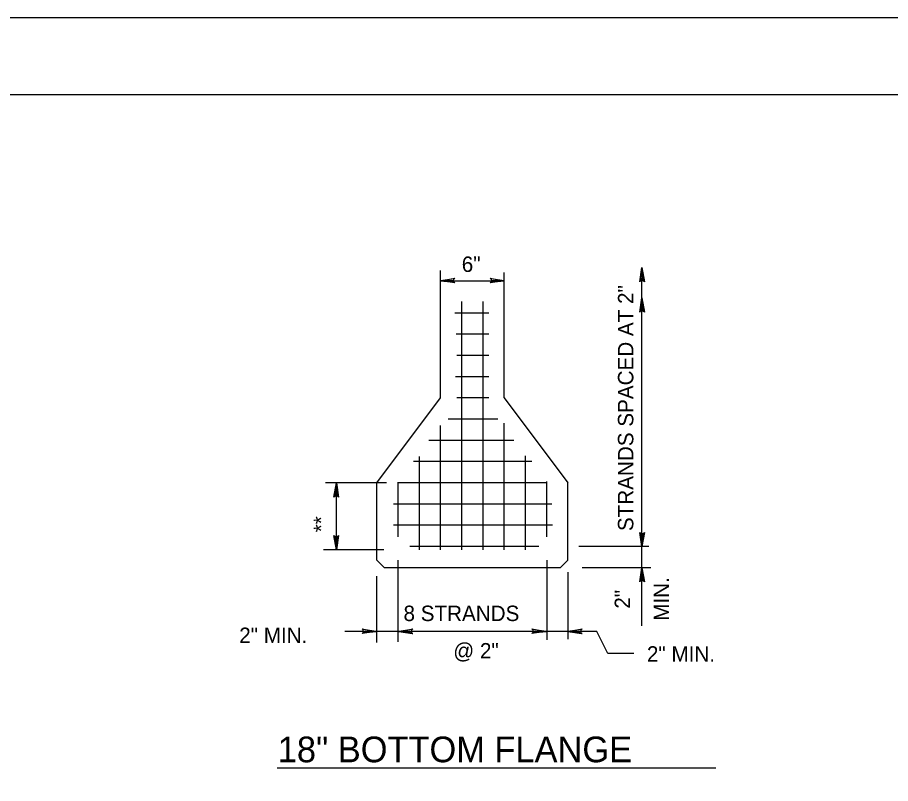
# Model space of a CAD drawing. Extents: x 637933 to 640019, y 298854 to 300042.
# Drawn here: x 639015.3 to 639185.1, y 299893.3 to 300042.1 of the extents above; entities that cross this region are included whole.
import ezdxf

# ---------------------------------------------------------------- set-up
doc = ezdxf.new("R2010")
doc.units = 0
doc.layers.add('1', color=7, linetype='Continuous')
doc.layers.add('PLT-BNDY', color=7, linetype='Continuous')

msp = doc.modelspace()

# ---------------------------------------------------------------- linework, layer by layer
at = {"layer": '1'}
for p, q in [((638864.93, 300027.12), (639650.94, 300027.12)), ((639097.58, 299968.18), (639097.58, 299992.93)), ((639109.96, 299968.18), (639109.96, 299992.55)), ((639136.71, 299939.3), (639136.71, 299991.49)), ((639097.58, 299990.93), (639109.96, 299990.93)), ((639101.71, 299938.68), (639101.71, 299986.93)), ((639105.83, 299938.68), (639105.83, 299986.93)), ((639106.96, 299984.68), (639100.33, 299984.68)), ((639106.96, 299980.55), (639100.58, 299980.55)), ((639106.96, 299976.43), (639100.71, 299976.43)), ((639106.96, 299972.3), (639100.46, 299972.3)), ((639085.21, 299951.68), (639097.58, 299968.18)), ((639106.96, 299968.18), (639100.71, 299968.18)), ((639109.96, 299968.18), (639122.33, 299951.68)), ((639108.71, 299964.05), (639099.08, 299964.05)), ((639097.58, 299938.68), (639097.58, 299962.8)), ((639109.96, 299938.68), (639109.96, 299963.3)), ((639111.83, 299959.93), (639095.33, 299959.93)), ((639115.33, 299955.8), (639092.33, 299955.8)), ((639093.46, 299938.68), (639093.46, 299956.8)), ((639114.08, 299938.68), (639114.08, 299956.93)), ((639087.08, 299951.68), (639075.21, 299951.68)), ((639077.33, 299938.68), (639077.33, 299951.68)), ((639085.21, 299936.68), (639085.21, 299951.68)), ((639118.33, 299951.68), (639089.21, 299951.68)), ((639089.33, 299941.18), (639089.33, 299951.8)), ((639118.21, 299941.18), (639118.21, 299951.93)), ((639122.33, 299936.68), (639122.33, 299951.68)), ((639119.21, 299947.55), (639088.46, 299947.55)), ((639119.33, 299943.43), (639088.46, 299943.43)), ((639086.58, 299938.68), (639074.83, 299938.68)), ((639116.71, 299939.3), (639091.58, 299939.3)), ((639138.08, 299939.3), (639124.46, 299939.3)), ((639136.71, 299923.9), (639136.71, 299939.3)), ((639085.21, 299936.68), (639086.71, 299935.18)), ((639120.83, 299935.18), (639086.71, 299935.18)), ((639089.33, 299920.8), (639089.33, 299936.68)), ((639118.21, 299936.68), (639118.21, 299921.18)), ((639122.33, 299936.68), (639120.83, 299935.18)), ((639138.46, 299935.18), (639125.08, 299935.18)), ((639085.21, 299920.68), (639085.21, 299933.55)), ((639122.33, 299934.3), (639122.33, 299921.3)), ((639085.08, 299922.8), (639078.96, 299922.8)), ((639089.46, 299922.8), (639085.08, 299922.8)), ((639118.08, 299922.8), (639089.46, 299922.8)), ((639122.33, 299922.8), (639118.08, 299922.8)), ((639127.94, 299922.8), (639122.33, 299922.8)), ((639130.11, 299918.52), (639127.94, 299922.8)), ((639135.13, 299918.52), (639130.11, 299918.52)), ((639151.1, 299896.21), (639065.84, 299896.21))]:
    msp.add_line(p, q, dxfattribs=at)
for points in [[(639136.33, 299990.88), (639136.58, 299991.01), (639136.71, 299993.51), (639136.33, 299990.88), (639136.33, 299990.76), (639136.71, 299993.51), (639136.83, 299991.01), (639137.08, 299990.88), (639136.71, 299993.51), (639137.21, 299990.76), (639137.08, 299990.88)], [(639100.21, 299990.68), (639100.08, 299990.8), (639097.58, 299990.93), (639100.21, 299990.68), (639100.33, 299990.55), (639097.58, 299990.93), (639100.08, 299991.05), (639100.21, 299991.3), (639097.58, 299990.93), (639100.33, 299991.43), (639100.21, 299991.3)], [(639107.33, 299991.3), (639107.46, 299991.05), (639109.96, 299990.93), (639107.33, 299991.3), (639107.21, 299991.43), (639109.96, 299990.93), (639107.46, 299990.8), (639107.33, 299990.68), (639109.96, 299990.93), (639107.21, 299990.55), (639107.33, 299990.68)], [(639136.33, 299985.01), (639136.58, 299985.13), (639136.71, 299987.63), (639136.33, 299985.01), (639136.33, 299984.88), (639136.71, 299987.63), (639136.83, 299985.13), (639137.08, 299985.01), (639136.71, 299987.63), (639137.21, 299984.88), (639137.08, 299985.01)], [(639076.96, 299949.05), (639077.21, 299949.18), (639077.33, 299951.68), (639076.96, 299949.05), (639076.83, 299948.93), (639077.33, 299951.68), (639077.46, 299949.18), (639077.58, 299949.05), (639077.33, 299951.68), (639077.71, 299948.93), (639077.58, 299949.05)], [(639137.08, 299941.93), (639136.83, 299941.8), (639136.71, 299939.3), (639137.08, 299941.93), (639137.21, 299942.05), (639136.71, 299939.3), (639136.58, 299941.8), (639136.46, 299941.93), (639136.71, 299939.3), (639136.33, 299942.05), (639136.46, 299941.93)], [(639077.58, 299941.3), (639077.46, 299941.18), (639077.33, 299938.68), (639077.58, 299941.3), (639077.71, 299941.43), (639077.33, 299938.68), (639077.21, 299941.18), (639076.96, 299941.3), (639077.33, 299938.68), (639076.83, 299941.43), (639076.96, 299941.3)], [(639136.33, 299932.55), (639136.58, 299932.68), (639136.71, 299935.18), (639136.33, 299932.55), (639136.33, 299932.43), (639136.71, 299935.18), (639136.83, 299932.68), (639137.08, 299932.55), (639136.71, 299935.18), (639137.21, 299932.43), (639137.08, 299932.55)], [(639082.46, 299923.18), (639082.46, 299922.93), (639085.08, 299922.8), (639082.46, 299923.18), (639082.33, 299923.3), (639085.08, 299922.8), (639082.58, 299922.68), (639082.46, 299922.55), (639085.08, 299922.8), (639082.33, 299922.43), (639082.46, 299922.55)], [(639092.08, 299922.43), (639091.96, 299922.68), (639089.46, 299922.8), (639092.08, 299922.43), (639092.21, 299922.43), (639089.46, 299922.8), (639091.96, 299922.93), (639092.08, 299923.18), (639089.46, 299922.8), (639092.21, 299923.3), (639092.08, 299923.18)], [(639115.46, 299923.18), (639115.58, 299922.93), (639118.08, 299922.8), (639115.46, 299923.18), (639115.33, 299923.3), (639118.08, 299922.8), (639115.58, 299922.68), (639115.46, 299922.55), (639118.08, 299922.8), (639115.33, 299922.43), (639115.46, 299922.55)], [(639115.46, 299923.18), (639115.58, 299922.93), (639118.08, 299922.8), (639115.46, 299923.18), (639115.33, 299923.3), (639118.08, 299922.8), (639115.58, 299922.68), (639115.46, 299922.55), (639118.08, 299922.8), (639115.33, 299922.43), (639115.46, 299922.55)], [(639124.96, 299922.43), (639124.83, 299922.68), (639122.33, 299922.8), (639124.96, 299922.43), (639125.08, 299922.43), (639122.33, 299922.8), (639124.83, 299922.93), (639124.96, 299923.18), (639122.33, 299922.8), (639125.08, 299923.3), (639124.96, 299923.18)]]:
    msp.add_lwpolyline(points, dxfattribs=at)
at = {"layer": 'PLT-BNDY'}
msp.add_lwpolyline([(638824.93, 300042.12), (639665.93, 300042.12), (639665.93, 299448.12), (638824.93, 299448.12)], close=True, dxfattribs=at)

# ---------------------------------------------------------------- texts
at = {"layer": '1'}
for s, height, p in [('6"', 3, (639101.7, 299992.67)), ('8 STRANDS', 3, (639090.38, 299924.82)), ('2" MIN.', 3, (639058.44, 299920.56)), ('@ 2"', 3, (639100.05, 299917.55)), ('2" MIN.', 3, (639137.7, 299916.93)), ('18" BOTTOM FLANGE', 5, (639065.93, 299897.38))]:
    msp.add_text(s, height=height, dxfattribs=at).set_placement(p)
for s, p in [('STRANDS SPACED AT 2"', (639135.06, 299942.31)), ('**', (639075.88, 299942.08)), ('MIN.', (639142.02, 299924.87)), ('2"', (639134.43, 299927.23))]:
    msp.add_text(s, height=3, rotation=90, dxfattribs=at).set_placement(p)

doc.saveas('drawing.dxf')
